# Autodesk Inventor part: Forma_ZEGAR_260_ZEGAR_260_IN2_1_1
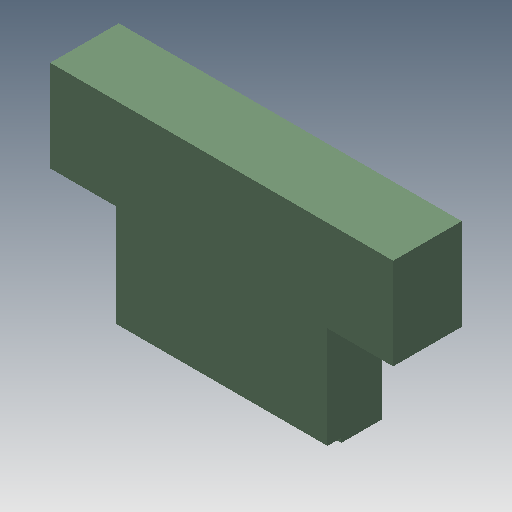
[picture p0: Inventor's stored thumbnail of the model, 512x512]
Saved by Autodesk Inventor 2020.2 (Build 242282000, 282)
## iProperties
Created: 2015-01
Part Number: Forma_ZEGAR_260_ZEGAR_260_IN2_1_1
Material: Ogólny
Document SubType Name: Modeling
Designer: F.Stasiak
Density: 1 g/cm^3
Appearance: Domyślna
Catalog Web Link: www.expertbooks.pl
Manager: www.cadconsulting.pl
Company: Fabian Stasiak CAD Consulting
Author: F.Stasiak
Subject: Zbiór ćwiczeń. Autodesk Inventor 2020. Kurs Professional
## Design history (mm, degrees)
node "Forma_ZEGAR_260_ZEGAR_260_IN2_Base"
feature "Bryła1::Forma_ZEGAR_260_ZEGAR_260_IN2_Base"
tag "Bryła wyprowadzona1"
node "Bryła1"
feature "Forma_ZEGAR_260_ZEGAR_260_IN2_Base_Bodies"
